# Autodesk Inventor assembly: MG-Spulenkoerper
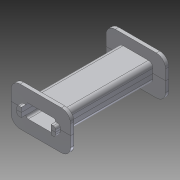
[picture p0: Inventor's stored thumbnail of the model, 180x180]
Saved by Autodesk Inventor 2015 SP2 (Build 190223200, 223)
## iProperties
Created: 2015-10
Part Number: MG-Spulenkoerper
Document SubType Name: Assembly
Designer: rYan
Author: rYan
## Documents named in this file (2)
- E:\TIGERs GIT\Hardware\mechanik\2016\Inventor\Kicker\MG-Spulenkoerper.iam
- E:\TIGERs GIT\Hardware\mechanik\2016\Inventor\Kicker\Spulenkoerper Haelfte.ipt
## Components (2 placed, 1 different names)
1. Spulenkoerper Haelfte:1 — Passend:1, Fluchtend:1, Fluchtend:2
2. Spulenkoerper Haelfte:2 — Passend:1, Fluchtend:1, Fluchtend:2
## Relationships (3: Flush 2, Mate 1)
- Passend:1 [Mate]: Spulenkoerper Haelfte:1 ↔ Spulenkoerper Haelfte:2
- Fluchtend:1 [Flush]: Spulenkoerper Haelfte:1 ↔ Spulenkoerper Haelfte:2
- Fluchtend:2 [Flush]: Spulenkoerper Haelfte:1 ↔ Spulenkoerper Haelfte:2
